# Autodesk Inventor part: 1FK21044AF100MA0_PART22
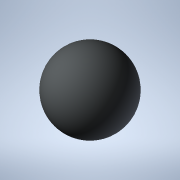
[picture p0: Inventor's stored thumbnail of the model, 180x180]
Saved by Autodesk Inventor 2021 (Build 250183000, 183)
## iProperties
Created: 2025-04
Part Number: 1FK21044AF100MA0_PART22
Material: Generic
Catalog Web Link: www.3dfindit.com
Description: -Servo synchronous motor
Document SubType Name: Modeling
Designer: psAdmin
Mass: 0.137258 g
Surface Area: 1.2868 cm^2
Volume: 0.137258 cm^3
Density: 1 g/cm^3
Appearance: PSOLRGB-212-217-219
Category: PARTsolutions
Title: 1FK21044AF100MA0_PART22
Author: Cadenas PARTsolutions
Comments: Servo synchronous motor
Sending System: PARTsolutions
Preprocessor: ST-DEVELOPER v19.3
PSOL_IDENT_0: {$CADENAS_DATA/23d-libs/siemens_ag/_cat_/ec/e4/1fk21044af100ma0.prj},216 {VTYP=3D},{NB=1FK21044AF100
PSOL_IDENT_1: MA0_PART22},{LINA=1FK21044AF100MA0_PART22},{NN=1FK21044AF100MA0_PART22},{NOPRJ=TRUE},{DATE=19.08.202
PSOL_IDENT_2: 5 14:01:05},{GEOMDATE=30.07.2025 02:01:01},{VERSION=},{LINEID=10},{WBVAR=},{WBNUMERIC=}  {NB=1FK2104
PSOL_IDENT_3: 4AF100MA0_PART22},{LINA=1FK21044AF100MA0_PART22},{KT=DUMMY},{PREVIEW=../../../_pool_/cb/72/p_d211_xx
PSOL_IDENT_4: _00434j.png},{DESCSHORT=SIMOTICS S-1FK2 HD, SINAMICS S210 3AC 400V-480V, 1.27 Nm, 3000 rpm},{DESCLON
PSOL_IDENT_5: G=SIMOTICS S-1FK2 HD servo motor M0=1.27 Nm; PN = 0.4 kW at nN=3000 rpm (380-480 V); PN = 0.2 kW at
PSOL_IDENT_6: nN=1500 rpm (200-240 V); with holding brake; degree of protection IP64; cylindrical shaft D19x40mm;
PSOL_IDENT_7: absolute encoder 22-bit + 12-bit multiturn (encoder AM22DQC); with OCC interface; plug size M17, rot
PSOL_IDENT_8: atable; SIMOTICS S-1FK2 servomotorfor a wide range of uses in industrial environments. SIMOTICS S‑1F
PSOL_IDENT_9: K2 servomotors are compact synchronous motors with a high dynamic performance that set themselves ap
PSOL_IDENT_10: art as a result of their high power density, degree of protection and overload capability. The motor
PSOL_IDENT_11: s are available in two variants: as High Dynamic variant (highest dynamic performance as a result of
PSOL_IDENT_12: the low intrinsic moment of inertia for applications demanding a high dynamic performance with low
PSOL_IDENT_13: moved masses) - and as Compact variant (precise and stable closed-loop control for medium up to larg
PSOL_IDENT_14: e moved masses as a result of a medium intrinsic moment of inertia). SIMOTICSS‑1FK2 servomotors full
PSOL_IDENT_15: y exploit their strengths in a system with the SINAMICSS210 frequency converter and simple connectio
PSOL_IDENT_16: n using the one cable connection (OCC). Advantages include the short control and positioning times,
PSOL_IDENT_17: fast and precise correction of disturbing quantities as well as stable control with a high dynamic p
PSOL_IDENT_18: erformance. The servo motors can be configured to address a wide range of requirements. For example
PSOL_IDENT_19: with and without holding brake, IP64 or IP65 degree of protection, singleturn or multiturn absolute
PSOL_IDENT_20: encoders - to name just a few. Further, the servomotors are available in different shaft heights ext
PSOL_IDENT_21: ending from 20 to 100. A shaft sealing ring is available to achieve an IP65 degree of protection and
PSOL_IDENT_22: for subsequent mounting at the motor or as spare part. SIMOTICS - the optimum motor for each and ev
PSOL_IDENT_23: ery motion control application.},{INTNO=195125043275},{SUPPLIERALTNO=1FK2104-4AF10-0MA0},{MANUID=1FK
PSOL_IDENT_24: 21044AF100MA0},{MANUNAME=Siemens},{MANUTYPEDESC=Synchronous motor 1FK2-HD 1.27 NM},{AAU732=SIMOTICS}
PSOL_IDENT_25: ,{AAO057=S-1FK2},{AAU734=SIMOTICS S-1FK2 HD servo motor M0=1.27 Nm; PN = 0.4 kW at nN=3000 rpm (380-
PSOL_IDENT_26: 480 V); PN = 0.2 kW at nN=1500 rpm (200-240 V); with holding brake; degree of protection IP64; cylin
PSOL_IDENT_27: drical shaft D19x40mm; absolute encoder 22-bit + 12-bit multiturn (encoder AM22DQC); with OCC interf
PSOL_IDENT_28: ace; plug size M17, rotatable;},{AAW338=Synchronous motor 1FK2-HD 1.27 NM},{AAO742=SIMOTICS},{AAO663=
PSOL_IDENT_29: 4042948694015},{NOCUPEROU=1},{PRICEQUANTITY=1},{QUANTITYMIN=1},{QUANTITYINT=1},{CTN=85015100},{COO=D
PSOL_IDENT_30: E},{AAO676=1FK2104-4AF10-0MA0},{AAO677=Siemens AG},{ORDERUNIT=C62},{CONTENTUNIT=C62}
NB: 1FK21044AF100MA0_PART22
NT: Servo synchronous motor
NBSYN: $MANUID._PART22
LINA: 1FK21044AF100MA0_PART22
CATALOG: SIEMENS
PREVIEW: ../../../_pool_/cb/72/p_d211_xx_00434j.png
DESCSHORT: SIMOTICS S-1FK2 HD, SINAMICS S210 3AC 400V-480V, 1.27 Nm, 3000 rpm
DESCLONG: SIMOTICS S-1FK2 HD servo motor M0=1.27 Nm; PN = 0.4 kW at nN=3000 rpm (380-480 V); PN = 0.2 kW at nN=1500 rpm (200-240 V); with holding brake; degree of protect
INTNO: 195125043275
SUPPLIERALTNO: 1FK2104-4AF10-0MA0
MANUID: 1FK21044AF100MA0
MANUNAME: Siemens
MANUTYPEDESC: Synchronous motor 1FK2-HD 1.27 NM
AAU732: SIMOTICS
AAO057: S-1FK2
AAU734: SIMOTICS S-1FK2 HD servo motor M0=1.27 Nm; PN = 0.4 kW at nN=3000 rpm (380-480 V); PN = 0.2 kW at nN=1500 rpm (200-240 V); with holding brake; degree of protect
AAW338: Synchronous motor 1FK2-HD 1.27 NM
AAO742: SIMOTICS
AAO663: 4042948694015.0
NOCUPEROU: 1
PRICEQUANTITY: 1
QUANTITYMIN: 1
QUANTITYINT: 1
CTN: 85015100
COO: DE
ARTICLENO: 1FK21044AF100MA0_PART22
BOMINFO: 1FK21044AF100MA0_PART22
CREATOR: CADENAS GmbH
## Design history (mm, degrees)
feature "2025_04_17_15_33_01_0673"
body "Solid1"
